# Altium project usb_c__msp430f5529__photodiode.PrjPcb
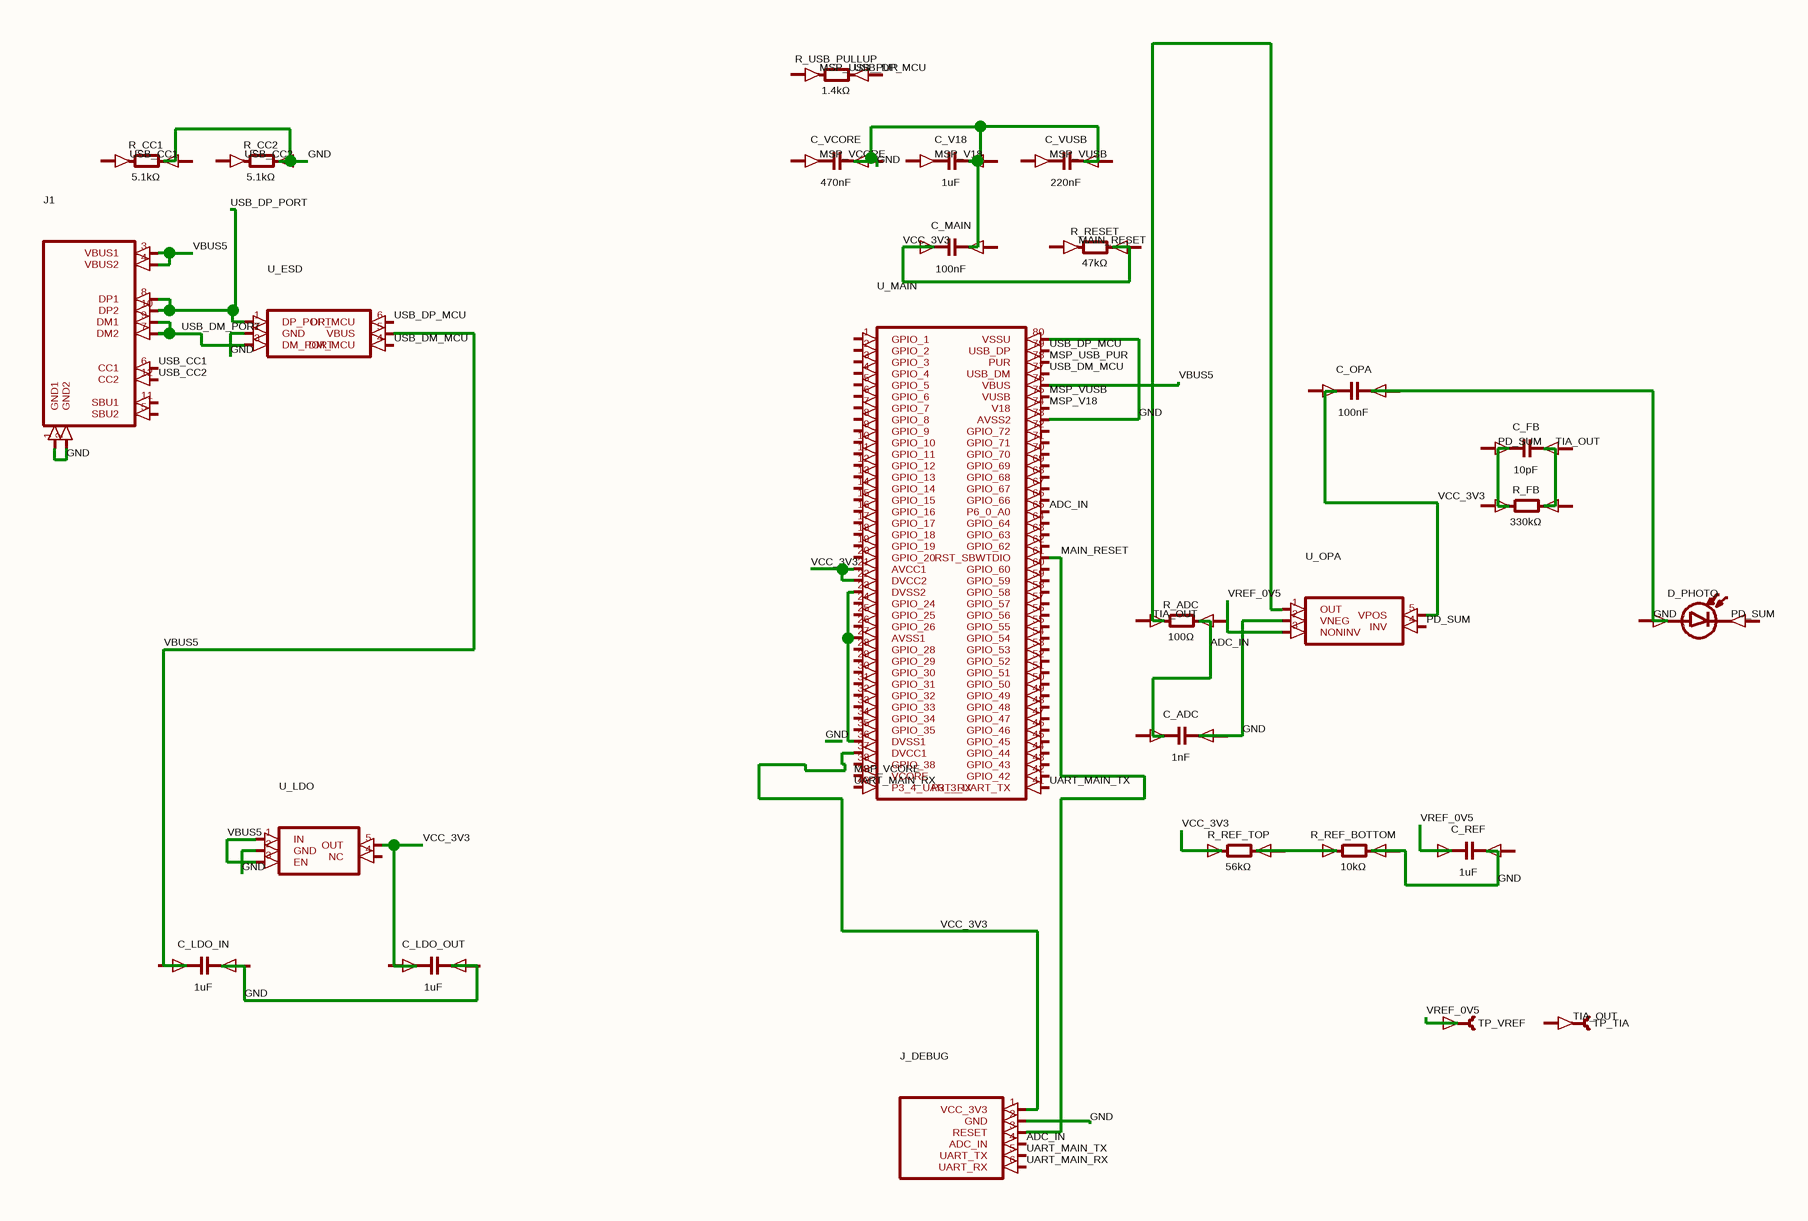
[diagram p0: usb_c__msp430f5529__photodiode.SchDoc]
1 sheet, 27 parts. Net scope: global (net labels, ports and power ports of the same name join across sheets).
Board file: usb_c__msp430f5529__photodiode.PcbDoc

## Sheet usb_c__msp430f5529__photodiode.SchDoc
size 200 x 150 mm

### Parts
C_ADC  1nF
C_FB  10pF
C_LDO_IN  1uF
C_LDO_OUT  1uF
C_MAIN  100nF
C_OPA  100nF
C_REF  1uF
C_V18  1uF
C_VCORE  470nF
C_VUSB  220nF
D_PHOTO  (no value)
J1  (no value)
J_DEBUG  (no value)
R_ADC  100Ω
R_CC1  5.1kΩ
R_CC2  5.1kΩ
R_FB  330kΩ
R_REF_BOTTOM  10kΩ
R_REF_TOP  56kΩ
R_RESET  47kΩ
R_USB_PULLUP  1.4kΩ
TP_TIA  (no value)
TP_VREF  (no value)
U_ESD  (no value)
U_LDO  (no value)
U_MAIN  (no value)
U_OPA  (no value)

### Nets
ADC_IN: J_DEBUG.4(ADC_IN) U_MAIN.65(P6_0_A0)
GND: C_ADC.2(neg) C_OPA.2(neg) C_REF.1(pos) J1.1(GND1) J1.2(GND2) J_DEBUG.2(GND) R_ADC.2(cathode) R_CC2.2(cathode) R_REF_BOTTOM.2(cathode) TP_VREF.1(pin1) U_ESD.2(GND) U_LDO.2(GND) U_MAIN.73(AVSS2) U_MAIN.80(VSSU) U_OPA.2(VNEG) U_OPA.3(NONINV)  [also labelled VREF_0V5]
MAIN_RESET: J_DEBUG.3(RESET) U_MAIN.61(RST_SBWTDIO)
MSP_USB_PUR: U_MAIN.78(PUR)
MSP_V18: U_MAIN.74(V18)
MSP_VCORE: U_MAIN.39(VCORE)
MSP_VUSB: U_MAIN.75(VUSB)
PD_SUM: U_OPA.4(INV)
TIA_OUT: U_OPA.1(OUT)
UART_MAIN_RX: J_DEBUG.6(UART_RX) U_MAIN.40(P3_4_UART_RX)
UART_MAIN_TX: J_DEBUG.5(UART_TX) U_MAIN.41(P3_3_UART_TX)
USB_CC1: J1.6(CC1)
USB_CC2: J1.12(CC2)
USB_DM_MCU: U_ESD.4(DM_MCU) U_MAIN.77(USB_DM)
USB_DM_PORT: J1.7(DM2) J1.9(DM1) U_ESD.3(DM_PORT)
USB_DP_MCU: U_ESD.6(DP_MCU) U_MAIN.79(USB_DP)
USB_DP_PORT: J1.8(DP1) J1.10(DP2) U_ESD.1(DP_PORT)
VBUS5: J1.3(VBUS1) J1.4(VBUS2) U_ESD.5(VBUS) U_LDO.1(IN) U_LDO.3(EN) U_MAIN.76(VBUS)
VCC_3V3: C_MAIN.1(pos) J_DEBUG.1(VCC_3V3) R_REF_TOP.1(anode) U_LDO.5(OUT) U_MAIN.21(AVCC1) U_MAIN.22(DVCC2) U_MAIN.37(DVCC1) U_OPA.5(VPOS)
NetR_REF_BOTTOM_1: R_REF_BOTTOM.1(anode) R_REF_TOP.2(cathode)
NetU_MAIN_23: U_MAIN.23(DVSS2) U_MAIN.27(AVSS1) U_MAIN.36(DVSS1)

Not connected (* = marked no-connect by the designer): C_ADC 1(pos); C_FB 1(pos) 2(neg); C_LDO_IN 1(pos) 2(neg); C_LDO_OUT 1(pos) 2(neg); C_MAIN 2(neg); C_OPA 1(pos); C_REF 2(neg); C_V18 1(pos) 2(neg); C_VCORE 1(pos) 2(neg); C_VUSB 1(pos) 2(neg); D_PHOTO 1(anode) 2(cathode); J1 5(SBU2) 11(SBU1); R_ADC 1(anode); R_CC1 1(anode) 2(cathode); R_CC2 1(anode); R_FB 1(anode) 2(cathode); R_RESET 1(anode) 2(cathode); R_USB_PULLUP 1(anode) 2(cathode); TP_TIA 1(pin1); U_LDO 4(NC); U_MAIN 1(GPIO_1) 2(GPIO_2) 3(GPIO_3) 4(GPIO_4) 5(GPIO_5) 6(GPIO_6) 7(GPIO_7) 8(GPIO_8) 9(GPIO_9) 10(GPIO_10) 11(GPIO_11) 12(GPIO_12) 13(GPIO_13) 14(GPIO_14) 15(GPIO_15) 16(GPIO_16) 17(GPIO_17) 18(GPIO_18) 19(GPIO_19) 20(GPIO_20) 24(GPIO_24) 25(GPIO_25) 26(GPIO_26) 28(GPIO_28) 29(GPIO_29) 30(GPIO_30) 31(GPIO_31) 32(GPIO_32) 33(GPIO_33) 34(GPIO_34) 35(GPIO_35) 38(GPIO_38) 42(GPIO_42) 43(GPIO_43) 44(GPIO_44) 45(GPIO_45) 46(GPIO_46) 47(GPIO_47) 48(GPIO_48) 49(GPIO_49) 50(GPIO_50) 51(GPIO_51) 52(GPIO_52) 53(GPIO_53) 54(GPIO_54) 55(GPIO_55) 56(GPIO_56) 57(GPIO_57) 58(GPIO_58) 59(GPIO_59) 60(GPIO_60) 62(GPIO_62) 63(GPIO_63) 64(GPIO_64) 66(GPIO_66) 67(GPIO_67) 68(GPIO_68) 69(GPIO_69) 70(GPIO_70) 71(GPIO_71) 72(GPIO_72)

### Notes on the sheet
- Labels drawn without touching a wire or pin: MAIN_RESET, MSP_USB_PUR, MSP_V18, MSP_VCORE, MSP_VUSB, PD_SUM, TIA_OUT, USB_CC1, USB_CC2, USB_DP_MCU

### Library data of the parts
C_ADC C_FB C_LDO_IN C_LDO_OUT C_MAIN C_OPA C_REF C_V18 C_VCORE C_VUSB = capacitor_right
D_PHOTO = photodiode_horz
J1 = J1
J_DEBUG = J_DEBUG
R_ADC R_CC1 R_CC2 R_FB R_REF_BOTTOM R_REF_TOP R_RESET R_USB_PULLUP = boxresistor_right
TP_TIA TP_VREF = testpoint_right
U_ESD = U_ESD
U_LDO = U_LDO
U_MAIN = U_MAIN
U_OPA = U_OPA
